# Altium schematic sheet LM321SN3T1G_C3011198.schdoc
size 127 x 101 mm
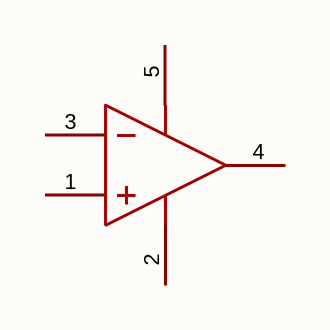
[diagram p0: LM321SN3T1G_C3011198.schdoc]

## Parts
U?  lm321sn3t1g  [SOT-23-5_L2.9-W1.6-P0.95-LS2.8-BL]  (value not drawn)

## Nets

Not connected (* = marked no-connect by the designer): U? 1(+IN) 2(-VS) 3(-IN) 4(OUT) 5(+VS)

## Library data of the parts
U? = lm321sn3t1g: 放大器数:1;轨到轨:-;增益带宽积(GBW):-;输入失调电压(Vos):5mV;压摆率(SR):-;输入偏置电流(Ib):250nA;; Manufacturer: TECH PUBLIC(台舟); Symbol: LM321SN3T1G_C3011198; AddInBom: yes; ModelId: 018c57e721114987ae90467fe9f1d259; ModelTransform: 114.96,110.236,0,0,0,0,0,0,0; Number of Channels: 1; Maximum Power Supply Range (Vdd-Vss): 36V; Vos - Input Offset Voltage: 5mV; Input Offset Voltage Drift(Vos TC): 7uV/℃; Ib - Input Bias Current: 250nA; Input Offset Current(Ios): 2nA; Common Mode Rejection Ratio(CMRR): 80dB; Input offset current drift(Ios TC): 10pA/℃; Quiescent Current: 700uA; Output Current: 40mA; Single supply: 3V~36V; Dual Supply: -20V~20V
